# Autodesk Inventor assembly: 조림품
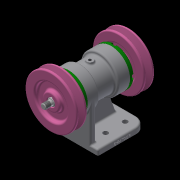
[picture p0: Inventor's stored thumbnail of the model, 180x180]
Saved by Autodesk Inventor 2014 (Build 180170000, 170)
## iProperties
Created: 2020-06
Part Number: 조림품
Document SubType Name: Assembly
Designer: kh
Author: kh
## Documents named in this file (8)
- C:\Users\kh\Desktop\700606V1034\조림품.iam
- C:\Users\kh\Desktop\700606V1034\본체.ipt
- C:\Users\kh\Desktop\700606V1034\베어링 6204.ipt
- C:\Users\kh\Desktop\700606V1034\축.ipt
- C:\Users\kh\Desktop\700606V1034\커버.ipt
- C:\Users\kh\Desktop\700606V1034\오일 실 20 32 5.ipt
- C:\Users\kh\Desktop\700606V1034\Ű 5x5x12.ipt
- C:\Users\kh\Desktop\700606V1034\V-벨트풀리.ipt
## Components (4 placed, 2 different names)
1. Ű 5x5x12:1 — Mate:17, Mate:18, Mate:23
2. Ű 5x5x12:2 — Mate:19, Mate:20, Mate:24
3. V-벨트풀리:1 — Mate:21, Mate:23, Flush:1
4. V-벨트풀리:2 — Mate:22, Mate:24, Flush:2
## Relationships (10: Mate 8, Flush 2)
- Mate:17: Ű 5x5x12:1
- Mate:18: Ű 5x5x12:1
- Mate:19: Ű 5x5x12:2
- Mate:20: Ű 5x5x12:2
- Mate:21: V-벨트풀리:1
- Mate:22: V-벨트풀리:2
- Mate:23: Ű 5x5x12:1 ↔ V-벨트풀리:1
- Mate:24: Ű 5x5x12:2 ↔ V-벨트풀리:2
- Flush:1: V-벨트풀리:1
- Flush:2: V-벨트풀리:2
